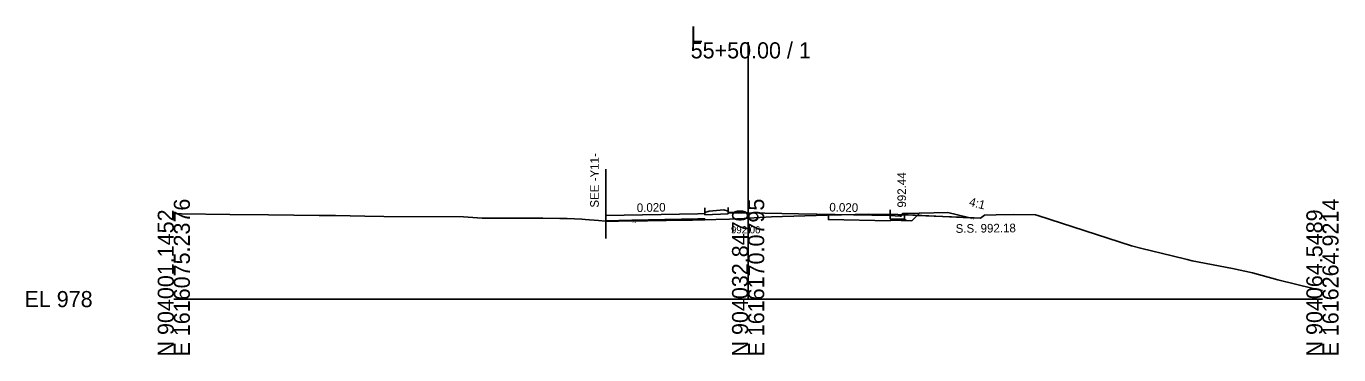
# Model space of a CAD drawing. Extents: x 1009 to 7438, y -1586 to 7964.
# Drawn here: x 5009.2 to 5237.7, y 3414 to 3471.2 of the extents above; entities that cross this region are included whole.
import ezdxf

# ---------------------------------------------------------------- set-up
doc = ezdxf.new("R2010")
doc.units = 0
for name, color, linetype in [('Exist Cross Section Cell', 7, 'Continuous'), ('Exist XS Center Line Elevation Label', 7, 'Continuous'), ('Exist XS Ground Line', 7, 'Continuous'), ('Prop XS Dump Level', 7, 'Continuous'), ('Prop XS Earthwork Shape', 7, 'Continuous'), ('Prop XS EOT Tick Mark', 7, 'Continuous'), ('Prop XS Finish Grade', 7, 'Continuous'), ('Prop XS Finish Grade CurbGutter', 7, 'Continuous'), ('Prop XS Finish Grade Earthwork', 7, 'Continuous'), ('Prop XS Finish Grade Pavement', 7, 'Continuous'), ('Prop XS Hydro Elevations', 7, 'Continuous'), ('Prop XS Pvmt Edge Slope', 7, 'Continuous'), ('Prop XS SE Text', 7, 'Continuous'), ('Prop XS Side Slope Text', 7, 'Continuous'), ('Prop XS SS Elevation Text', 7, 'Continuous'), ('Prop XS Subgrade CurbGutter', 7, 'Continuous'), ('Prop XS Subgrade Earthwork', 7, 'Continuous')]:
    doc.layers.add(name, color=color, linetype=linetype)

msp = doc.modelspace()

# ---------------------------------------------------------------- linework, layer by layer
at = {"layer": 'Exist Cross Section Cell'}
for p, q in [((5134.89, 3423.73), (5134.89, 3468.44)), ((5034.89, 3423.73), (5134.89, 3423.73)), ((5134.89, 3423.73), (5234.89, 3423.73))]:
    msp.add_line(p, q, dxfattribs=at)
at = {"layer": 'Exist XS Ground Line'}
for p, q in [((5034.89, 3438.63), (5036.23, 3438.6)), ((5036.23, 3438.6), (5044.62, 3438.43)), ((5044.62, 3438.43), (5051.4, 3438.41)), ((5051.4, 3438.41), (5060.21, 3438.3)), ((5060.21, 3438.3), (5063.02, 3438.26)), ((5063.02, 3438.26), (5068.17, 3438.19)), ((5068.17, 3438.19), (5071.48, 3438.12)), ((5071.48, 3438.12), (5085.31, 3438.04)), ((5085.31, 3438.04), (5088.57, 3437.82)), ((5088.57, 3437.82), (5090.72, 3437.82)), ((5090.72, 3437.82), (5098.06, 3437.83)), ((5098.06, 3437.83), (5099.14, 3437.82)), ((5099.14, 3437.82), (5102.12, 3437.78)), ((5102.12, 3437.78), (5103.41, 3437.77)), ((5103.41, 3437.77), (5105.92, 3437.63)), ((5105.92, 3437.63), (5106.52, 3437.59)), ((5106.52, 3437.59), (5108.85, 3437.41)), ((5108.85, 3437.41), (5110.05, 3437.32)), ((5110.05, 3437.32), (5110.57, 3437.31)), ((5110.57, 3437.31), (5111.72, 3437.32)), ((5111.72, 3437.32), (5112.35, 3437.32)), ((5112.35, 3437.32), (5113.21, 3437.33)), ((5113.21, 3437.33), (5114.67, 3437.35)), ((5114.67, 3437.35), (5117.36, 3437.34)), ((5117.36, 3437.34), (5120.63, 3437.42)), ((5120.63, 3437.42), (5125.18, 3437.49)), ((5125.18, 3437.49), (5129.29, 3437.6)), ((5129.29, 3437.6), (5131.65, 3437.67)), ((5131.65, 3437.67), (5134.19, 3437.75)), ((5134.19, 3437.75), (5134.89, 3437.79)), ((5134.89, 3437.79), (5138.95, 3438.04)), ((5138.95, 3438.04), (5148.64, 3438.36)), ((5148.64, 3438.36), (5151.16, 3438.42)), ((5151.16, 3438.42), (5155.93, 3438.51)), ((5155.93, 3438.51), (5160.95, 3438.44)), ((5160.95, 3438.44), (5162.78, 3438.38)), ((5162.78, 3438.38), (5173.53, 3437.9)), ((5173.53, 3437.9), (5174.27, 3437.87)), ((5174.27, 3437.87), (5175.33, 3437.84)), ((5175.33, 3437.84), (5176.07, 3438.32)), ((5176.07, 3438.32), (5178.11, 3438.4)), ((5178.11, 3438.4), (5181.03, 3438.48)), ((5181.03, 3438.48), (5184.93, 3438.4)), ((5184.93, 3438.4), (5185.31, 3438.28)), ((5185.31, 3438.28), (5201.65, 3433.03)), ((5201.65, 3433.03), (5203.42, 3432.52)), ((5203.42, 3432.52), (5208.74, 3431.26)), ((5208.74, 3431.26), (5211.33, 3430.6)), ((5211.33, 3430.6), (5212.19, 3430.41)), ((5212.19, 3430.41), (5219.23, 3429.06)), ((5219.23, 3429.06), (5222.74, 3428.3)), ((5222.74, 3428.3), (5227.13, 3427.09)), ((5227.13, 3427.09), (5233.28, 3425.56)), ((5233.28, 3425.56), (5234.89, 3425.21))]:
    msp.add_line(p, q, dxfattribs=at)
at = {"layer": 'Prop XS Dump Level'}
for p, q in [((5110.14, 3438.28), (5126.14, 3438.6)), ((5110.14, 3438.28), (5126.14, 3438.6)), ((5126.14, 3438.6), (5127.35, 3438.62)), ((5126.14, 3438.6), (5127.35, 3438.62)), ((5131.43, 3438.7), (5134.89, 3438.77)), ((5131.43, 3438.7), (5134.89, 3438.77)), ((5134.89, 3438.77), (5143.64, 3438.6)), ((5134.89, 3438.77), (5143.64, 3438.6)), ((5143.64, 3438.6), (5159.64, 3438.28)), ((5143.64, 3438.6), (5159.64, 3438.28))]:
    msp.add_line(p, q, dxfattribs=at)
at = {"layer": 'Prop XS Earthwork Shape'}
for points in [[(5112.35, 3437.32), (5113.21, 3437.33), (5114.67, 3437.35), (5114.67, 3437.45), (5110.14, 3437.36), (5110.14, 3437.32), (5110.57, 3437.31), (5111.72, 3437.32)], [(5114.67, 3437.35), (5117.36, 3437.34), (5120.63, 3437.42), (5125.18, 3437.49), (5127.34, 3437.55), (5127.35, 3437.7), (5126.14, 3437.68), (5114.67, 3437.45)], [(5148.87, 3438.36), (5151.16, 3438.42), (5155.93, 3438.51), (5160.95, 3438.44), (5161.64, 3438.42), (5161.61, 3438.29), (5161.52, 3438.19), (5161.39, 3438.17), (5159.64, 3438.28), (5159.64, 3437.7), (5161.14, 3437.67), (5162.14, 3437.65), (5162.4, 3437.39), (5159.64, 3437.45), (5159.64, 3437.36), (5148.87, 3437.57)], [(5159.64, 3437.7), (5161.14, 3437.67), (5162.14, 3437.65), (5162.14, 3438.4), (5161.64, 3438.42), (5161.61, 3438.29), (5161.52, 3438.19), (5161.39, 3438.17), (5159.64, 3438.28)], [(5162.14, 3438.4), (5162.78, 3438.38), (5164.33, 3438.31), (5163.39, 3437.37), (5162.4, 3437.39), (5162.14, 3437.65)], [(5164.33, 3438.31), (5164.73, 3438.71), (5169.64, 3438.81), (5173.27, 3437.91)]]:
    msp.add_lwpolyline(points, close=True, dxfattribs=at)
at = {"layer": 'Prop XS EOT Tick Mark'}
for p, q in [((5110.14, 3434.26), (5110.14, 3446.35)), ((5127.35, 3438.62), (5127.35, 3439.62)), ((5131.43, 3438.7), (5131.43, 3439.7)), ((5159.64, 3438.28), (5159.64, 3439.28))]:
    msp.add_line(p, q, dxfattribs=at)
at = {"layer": 'Prop XS Finish Grade'}
msp.add_line((5162.14, 3438.66), (5164.73, 3438.71), dxfattribs=at)
at = {"layer": 'Prop XS Finish Grade CurbGutter'}
for p, q in [((5127.35, 3438.79), (5128.1, 3439.04)), ((5127.35, 3438.62), (5127.35, 3438.79)), ((5128.1, 3439.04), (5130.68, 3439.25)), ((5131.43, 3439.01), (5130.68, 3439.25)), ((5131.43, 3438.84), (5131.43, 3439.01)), ((5159.64, 3438.28), (5161.39, 3438.17)), ((5161.39, 3438.17), (5161.52, 3438.19)), ((5161.52, 3438.19), (5161.61, 3438.29)), ((5161.61, 3438.29), (5161.68, 3438.54)), ((5161.68, 3438.54), (5161.77, 3438.63)), ((5161.89, 3438.66), (5161.77, 3438.63)), ((5162.14, 3438.66), (5161.89, 3438.66))]:
    msp.add_line(p, q, dxfattribs=at)
at = {"layer": 'Prop XS Finish Grade Earthwork'}
for p, q in [((5164.73, 3438.71), (5169.64, 3438.81)), ((5169.64, 3438.81), (5173.27, 3437.91))]:
    msp.add_line(p, q, dxfattribs=at)
at = {"layer": 'Prop XS Finish Grade Pavement'}
for p, q in [((5126.14, 3438.6), (5127.35, 3438.62)), ((5131.43, 3438.84), (5134.89, 3438.77)), ((5134.89, 3438.77), (5143.64, 3438.6)), ((5143.64, 3438.6), (5159.64, 3438.28))]:
    msp.add_line(p, q, dxfattribs=at)
msp.add_lwpolyline([(5110.14, 3437.32), (5110.14, 3438.28), (5126.14, 3438.6)], dxfattribs=at)
at = {"layer": 'Prop XS Pvmt Edge Slope'}
for p, q in [((5161.14, 3437.67), (5162.14, 3437.65)), ((5162.14, 3437.65), (5162.4, 3437.39))]:
    msp.add_line(p, q, dxfattribs=at)
at = {"layer": 'Prop XS Subgrade CurbGutter'}
for p, q in [((5127.35, 3438.62), (5127.35, 3438.37)), ((5127.35, 3438.37), (5131.43, 3438.59)), ((5131.43, 3438.84), (5131.43, 3438.59)), ((5159.64, 3438.28), (5159.64, 3437.7)), ((5159.64, 3437.7), (5162.14, 3437.65)), ((5162.14, 3437.65), (5162.14, 3438.66))]:
    msp.add_line(p, q, dxfattribs=at)
at = {"layer": 'Prop XS Subgrade Earthwork'}
for p, q in [((5114.67, 3437.45), (5110.14, 3437.36)), ((5110.14, 3437.32), (5110.14, 3437.36)), ((5110.14, 3437.36), (5110.14, 3437.32)), ((5114.67, 3437.45), (5126.14, 3437.68)), ((5114.67, 3437.45), (5114.67, 3437.35)), ((5114.67, 3437.45), (5114.67, 3437.35)), ((5126.14, 3437.68), (5127.35, 3437.7)), ((5127.35, 3437.7), (5127.34, 3437.55)), ((5148.87, 3437.57), (5148.87, 3438.36)), ((5159.64, 3437.36), (5148.87, 3437.57)), ((5159.64, 3437.36), (5159.64, 3437.45)), ((5159.64, 3437.45), (5163.39, 3437.37)), ((5163.39, 3437.37), (5164.73, 3438.71))]:
    msp.add_line(p, q, dxfattribs=at)

# ---------------------------------------------------------------- texts
at = {"layer": 'Exist Cross Section Cell'}
for s, p in [('L', (5124.89, 3468.44)), ('55+50.00 / 1', (5124.89, 3465.64)), ('EL 978', (5008.89, 3422.33))]:
    msp.add_text(s, height=2.8, dxfattribs=at).set_placement(p)
for s, p in [('E 1616075.2376', (5037.69, 3413.73)), ('E 1616170.0795', (5137.69, 3413.73)), ('E 1616264.9214', (5237.69, 3413.73)), ('N 904001.1452', (5034.89, 3413.73)), ('N 904032.8470', (5134.89, 3413.73)), ('N 904064.5489', (5234.89, 3413.73))]:
    msp.add_text(s, height=2.8, rotation=90, dxfattribs=at).set_placement(p)
at = {"layer": 'Exist XS Center Line Elevation Label'}
msp.add_text('992.06', height=1.25, dxfattribs=at).set_placement((5131.91, 3435.17))
at = {"layer": 'Prop XS Dump Level'}
for p in [(5114.67, 3437.05), (5114.67, 3437.05), (5114.67, 3437.05), (5173.53, 3437.6)]:
    msp.add_text('Eop', height=0.3, dxfattribs=at).set_placement(p)
at = {"layer": 'Prop XS Hydro Elevations'}
for s, p in [('SEE -Y11-', (5108.89, 3439.66)), ('992.44', (5162.39, 3439.66))]:
    msp.add_text(s, height=1.5, rotation=90, dxfattribs=at).set_placement(p)
at = {"layer": 'Prop XS SE Text'}
for rotation, p in [(1.1458, (5115.52, 3438.88)), (358.8542, (5149.02, 3438.99))]:
    msp.add_text('0.020', height=1.5, rotation=rotation, dxfattribs=at).set_placement(p)
at = {"layer": 'Prop XS Side Slope Text'}
msp.add_text('4:1', height=1.5, rotation=345.9638, dxfattribs=at).set_placement((5173.26, 3440))
at = {"layer": 'Prop XS SS Elevation Text'}
msp.add_text('S.S. 992.18', height=1.5, rotation=0.5729, dxfattribs=at).set_placement((5171.03, 3435.26))

doc.saveas('drawing.dxf')
